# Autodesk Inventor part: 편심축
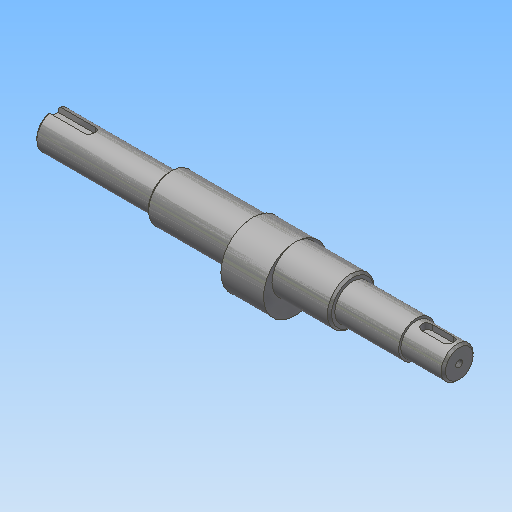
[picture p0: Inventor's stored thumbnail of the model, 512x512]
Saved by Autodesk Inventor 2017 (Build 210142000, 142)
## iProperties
Created: 2016-05
Part Number: 편심축
Document SubType Name: Modeling
Designer: mduedu
Density: 7.86 g/cm^3
Material: 강철, 연강
Appearance: 강철
Author: mduedu
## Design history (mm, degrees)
sketch "스케치1"
  geometry: L1 (-40.5, 11)-(-40.5, 8.5); L2 (45.5, 11)-(45.5, 8.5); L3 (-95.5, 0)-(95.5, 0); L4 (-40.5, 11)-(45.5, 11); L5 (45.5, 11)-(45.5, 8.5); L6 (-40.5, 11)-(-40.5, 8.5); L7 (-40.5, 8.5)-(-95.5, 8.5); L8 (-95.5, 8.5)-(-95.5, 0); L9 (45.5, 8.5)-(75.5, 8.5); L10 (95.5, 7.5)-(95.5, 0); L11 (75.5, 8.5)-(75.5, 7.5); L12 (75.5, 7.5)-(95.5, 7.5); 1 further point
  constraints: 24 end point, 9 perpendicular, 2 midpoint, 1 collinear, 1 horizontal
  dimensions: "d0" = 22 diameter of L4 L3; "d1" = 17 diameter of L7 L3; "d2" = 55 distance between parallel lines of L8 L1; "d3" = 50 distance between parallel lines of L10 L2; "d4" = 15 diameter of L12 L3; "d5" = 20 distance between parallel lines of L10 L11; "d29" = 86 distance of L1.start L2.start
revolve "회전1" stored, may be unused: angle "d6" = 90 deg
node "작업 평면7"
node "작업 평면9"
sketch "스케치2"
  geometry: C1 r 11 at (0, 0); C2 r 15 at (0, -4); C3 r 11 at (0, 0); 2 further points
  constraints: 3 centre point, 2 coincident, 1 concentric, 1 vertical alignment
  dimensions: "d9" = 4 distance of point (0, 0) C2.centre; "d10" = 30 diameter of C2
extrude "돌출1" join sketch "스케치2" stored distance "d11" = 20; taper "d12" = 0 deg
chamfer "모따기1" distance "d17" = 1; stored, may be unused: second distance "d18" = 2, angle "d19" = 45 deg
node "작업 평면4"
sketch "스케치4"
  geometry: L1 (-10, -6.5)-(-10, 6.5) reference; L2 (-5, 2.5)-(5, 2.5); L3 (5, -2.5)-(-5, -2.5); A1 r 2.5 centre (5, 0) between (5, -2.5) and (5, 2.5); A2 r 2.5 centre (-5, 0) between (-5, 2.5) and (-5, -2.5); 2 further points
  constraints: 4 end point, 4 point on circle, 4 tangent, 2 centre point, 1 horizontal alignment, 1 midpoint, 1 parallel, 1 perpendicular
  dimensions: "d20" = 5 distance between parallel lines of L3 L2; "d21" = 15 dimension on A1 A2; "d22" = 2.5 distance edge to line of A2 L1
extrude "돌출3" cut sketch "스케치4" distance "d23" = 3; taper "d24" = 0 deg
node "작업 평면5"
sketch "스케치5"
  geometry: L1 (27.5, 7.5)-(27.5, -7.5) reference; L2 (27.5, 2.5)-(10, 2.5); L3 (10, -2.5)-(27.5, -2.5); A1 r 2.5 centre (10, 0) between (10, 2.5) and (10, -2.5); 2 further points
  constraints: 4 end point, 2 perpendicular, 2 point on circle, 2 point on line, 2 tangent, 1 centre point, 1 horizontal alignment, 1 midpoint
  dimensions: "d25" = 5 distance between parallel lines of L3 L2; "d26" = 20 dimension on A1 L1
extrude "돌출4" cut sketch "스케치5" distance "d27" = 3; taper "d28" = 0 deg
hole "구멍1" diameter "d34" = 3.242; stored, may be unused: countersink angle "d38" = 90 deg, drill point angle "d40" = 118 deg; dims "d35" = 9, "d36" = 4, "d37" = 2, "d39" = 11, "d43" = 10, "d44" = 10
node "솔리드1"
other parameters: "d31" = -37
